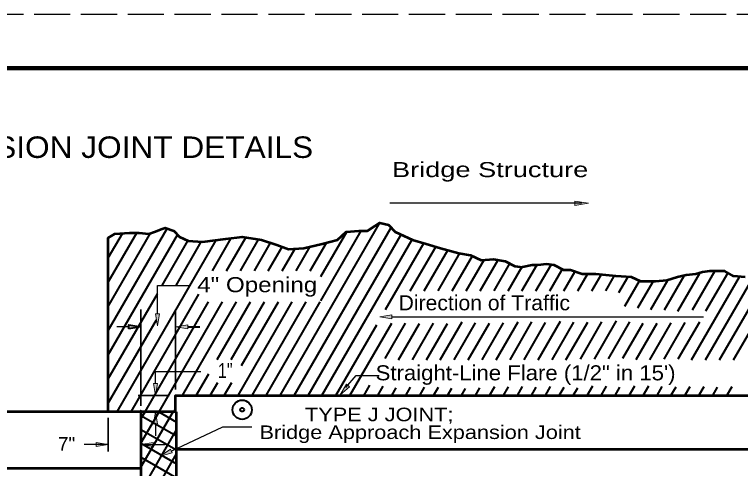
# Model space of a CAD drawing. Extents: x 14 to 49.3, y 28 to 50.
# Drawn here: x 36.45 to 43.21, y 45.82 to 50.04 of the extents above; entities that cross this region are included whole.
import ezdxf

# ---------------------------------------------------------------- set-up
doc = ezdxf.new("R2010")
doc.units = 0
doc.header["$LTSCALE"] = 0.056
doc.header["$PDMODE"] = 32
doc.header["$PDSIZE"] = 0.028
doc.linetypes.add('LONG_DASHED', pattern=[7.5, 6, -1.5])
for name, color, linetype, lineweight in [('1', 7, 'Continuous', 35), ('3', 7, 'Continuous', 13), ('6', 7, 'Continuous', 13)]:
    doc.layers.add(name, color=color, linetype=linetype, lineweight=lineweight)

msp = doc.modelspace()

# ---------------------------------------------------------------- hatches: boundary and pattern name
at = {"layer": '1'}
for points in [[(37.51475, 47.11892), (37.51475, 47.15642), (37.62725, 47.13758), (37.62725, 47.13758)], [(38.06233, 47.11892), (38.06233, 47.15642), (37.94983, 47.13758), (37.94983, 47.13758)], [(37.78058, 46.61067), (37.74308, 46.61067), (37.76183, 46.49817), (37.76183, 46.49817)], [(37.78058, 46.23517), (37.74308, 46.23517), (37.76183, 46.34767), (37.76183, 46.34767)], [(37.20992, 46.02475), (37.20992, 46.06225), (37.32242, 46.04342), (37.32242, 46.04342)], [(37.73975, 46.02475), (37.73975, 46.06225), (37.62725, 46.04342), (37.62725, 46.04342)]]:
    msp.add_hatch(color=256, dxfattribs=at).paths.add_polyline_path(points)
at = {"layer": '3'}
for points in [[(41.66558, 48.3085), (41.66558, 48.26683), (41.79058, 48.28767), (41.79058, 48.28767)], [(37.7985, 47.25958), (37.76092, 47.25958), (37.77975, 47.14708), (37.77975, 47.14708)], [(39.96283, 47.213), (39.96283, 47.2505), (39.85033, 47.23175), (39.85033, 47.23175)], [(39.56692, 46.5785), (39.5385, 46.603), (39.47925, 46.50558), (39.47925, 46.50558)], [(37.9165, 45.96458), (37.9005, 45.9985), (37.80658, 45.93392), (37.80658, 45.93392)]]:
    msp.add_hatch(color=256, dxfattribs=at).paths.add_polyline_path(points)

# ---------------------------------------------------------------- linework, layer by layer
at = {"layer": '1', "linetype": 'LONG_DASHED', "lineweight": 25}
msp.add_line((49.17658, 50.04392), (13.97658, 50.04392), dxfattribs=at)
at = {"layer": '1', "lineweight": 158}
msp.add_line((49.09325, 49.54392), (16.59325, 49.54392), dxfattribs=at)
at = {"layer": '1', "lineweight": 40}
for p, q in [((38.92158, 46.49817), (39.85, 48.10625)), ((37.3225, 47.1035), (37.8705, 48.05275)), ((39.0515, 46.49817), (39.95467, 48.06267)), ((39.301, 47.3805), (39.67675, 48.03117)), ((37.3225, 47.5535), (37.58742, 48.01233)), ((37.3225, 47.3285), (37.71508, 48.00858)), ((37.3225, 47.7785), (37.45483, 48.00783)), ((37.3225, 46.8785), (37.96692, 47.99467)), ((38.29233, 47.65825), (38.46783, 47.96233)), ((38.42225, 47.65825), (38.60183, 47.9695)), ((39.18133, 46.49817), (40.04675, 47.99708)), ((39.301, 47.6055), (39.54158, 48.02217)), ((37.40575, 46.34767), (38.32758, 47.94433)), ((37.82458, 47.52325), (38.06417, 47.93817)), ((37.95458, 47.52325), (38.1885, 47.92858)), ((38.55208, 47.65825), (38.72092, 47.95075)), ((38.682, 47.65825), (38.83242, 47.91875)), ((39.20158, 47.65825), (39.35233, 47.91942)), ((39.31125, 46.49817), (40.14908, 47.94933)), ((39.90358, 47.29925), (40.25933, 47.91533)), ((38.81192, 47.65825), (38.94108, 47.88208)), ((38.94183, 47.65825), (39.06175, 47.866)), ((39.07175, 47.65825), (39.20233, 47.88467)), ((40.13325, 47.472), (40.37092, 47.88367)), ((40.26317, 47.472), (40.48292, 47.8525)), ((40.39308, 47.472), (40.5955, 47.8225)), ((40.523, 47.472), (40.71058, 47.797)), ((40.65292, 47.472), (40.81958, 47.76075)), ((40.78283, 47.472), (40.94942, 47.76058)), ((40.91275, 47.472), (41.05933, 47.726)), ((41.04267, 47.472), (41.17042, 47.6935)), ((41.1725, 47.472), (41.31075, 47.7115)), ((41.30242, 47.472), (41.44292, 47.71533)), ((41.43233, 47.472), (41.54783, 47.67208)), ((41.56225, 47.472), (41.66525, 47.65042)), ((41.69217, 47.472), (41.7815, 47.62675)), ((42.62192, 47.2825), (42.827, 47.63775)), ((42.75958, 47.29592), (42.96692, 47.655)), ((42.88458, 47.28742), (43.08733, 47.63867)), ((41.822, 47.472), (41.9085, 47.62175)), ((41.95192, 47.472), (42.03125, 47.6095)), ((42.07267, 47.45608), (42.15617, 47.60075)), ((42.13042, 47.33117), (42.26625, 47.5665)), ((42.25042, 47.314), (42.393, 47.56092)), ((42.3725, 47.3005), (42.52967, 47.57275)), ((42.49983, 47.296), (42.683, 47.61325)), ((42.75083, 46.83067), (43.19675, 47.603)), ((42.88075, 46.83067), (43.31367, 47.5805)), ((43.01067, 46.83067), (43.42575, 47.54975)), ((37.3225, 46.6535), (37.77975, 47.4455)), ((37.53567, 46.34767), (38.167, 47.44133)), ((37.6655, 46.34767), (38.25592, 47.37025)), ((37.79542, 46.34767), (38.38583, 47.37025)), ((38.01217, 46.49817), (38.51575, 47.37025)), ((38.33508, 46.8325), (38.64567, 47.37025)), ((38.465, 46.8325), (38.7755, 47.37025)), ((38.53175, 46.49817), (39.03533, 47.37025)), ((38.56358, 46.77817), (38.90542, 47.37025)), ((38.66167, 46.49817), (39.16525, 47.37025)), ((38.79158, 46.49817), (39.29517, 47.37025)), ((43.1405, 46.83067), (43.45375, 47.37325)), ((37.3225, 46.4285), (37.77025, 47.20408)), ((39.44117, 46.49817), (39.82192, 47.15775)), ((39.57108, 46.49817), (39.96067, 47.17308)), ((39.90017, 46.843), (40.08983, 47.17175)), ((40.0235, 46.83183), (40.2185, 47.16958)), ((40.15275, 46.83067), (40.34983, 47.17208)), ((40.28267, 46.83067), (40.478, 47.16908)), ((40.41258, 46.83067), (40.6165, 47.184)), ((40.5425, 46.83067), (40.74133, 47.17525)), ((40.67233, 46.83067), (40.87, 47.173)), ((40.80225, 46.83067), (41.00108, 47.17508)), ((40.93217, 46.83067), (41.13575, 47.18333)), ((41.06208, 46.83067), (41.26542, 47.18283)), ((41.192, 46.83067), (41.39217, 47.17742)), ((41.32183, 46.83067), (41.52925, 47.18975)), ((41.45175, 46.83067), (41.65358, 47.18017)), ((41.58167, 46.83067), (41.78417, 47.18133)), ((41.71567, 46.83775), (41.9165, 47.18558)), ((41.84575, 46.83783), (42.05092, 47.19333)), ((41.97675, 46.84), (42.17592, 47.185)), ((42.10967, 46.84517), (42.29883, 47.17292)), ((42.23383, 46.83533), (42.42892, 47.17325)), ((42.36108, 46.83067), (42.56, 47.17525)), ((42.49483, 46.83733), (42.69158, 47.17817)), ((42.626, 46.83958), (42.82575, 47.1855)), ((38.06233, 47.13767), (38.17483, 47.13767)), ((38.14208, 46.49817), (38.2595, 46.70167)), ((38.272, 46.49817), (38.34283, 46.62092)), ((38.40192, 46.49817), (38.47275, 46.62092)), ((39.69933, 46.49517), (39.75683, 46.59483)), ((39.83083, 46.49817), (39.88217, 46.58708)), ((39.96075, 46.49817), (40.00258, 46.57067)), ((40.09067, 46.49817), (40.13625, 46.57708)), ((40.22058, 46.49817), (40.26508, 46.57525)), ((40.3505, 46.49817), (40.396, 46.57683)), ((40.48033, 46.49817), (40.51975, 46.56625)), ((40.61025, 46.49817), (40.64767, 46.563)), ((40.74017, 46.49817), (40.781, 46.56875)), ((40.87008, 46.49817), (40.9185, 46.582)), ((41, 46.49817), (41.04692, 46.57933)), ((41.12983, 46.49817), (41.17808, 46.58158)), ((41.25975, 46.49817), (41.30433, 46.57525)), ((41.38967, 46.49817), (41.43808, 46.58192)), ((41.51967, 46.49817), (41.565, 46.57675)), ((41.6495, 46.49817), (41.692, 46.57175)), ((41.77942, 46.49817), (41.83175, 46.58875)), ((41.90933, 46.49817), (41.96008, 46.58625)), ((42.03925, 46.49817), (42.08392, 46.57567)), ((42.16917, 46.49817), (42.22175, 46.58942)), ((42.299, 46.49817), (42.35158, 46.58942)), ((42.42892, 46.49817), (42.47783, 46.58292)), ((42.55883, 46.49817), (42.60558, 46.579)), ((42.68875, 46.49817), (42.73808, 46.5835)), ((42.81867, 46.49817), (42.86758, 46.58283)), ((42.9485, 46.49817), (42.99308, 46.57525)), ((43.07842, 46.49817), (43.127, 46.58208)), ((37.62725, 45.83133), (37.92533, 46.34767)), ((37.62725, 46.05633), (37.79542, 46.34767)), ((37.62725, 46.28133), (37.6655, 46.34767)), ((37.79375, 46.34767), (37.95883, 46.25233)), ((37.62725, 46.31392), (37.95883, 46.12242)), ((37.62725, 46.184), (37.95883, 45.9925)), ((37.62725, 45.60633), (37.95883, 46.18083)), ((37.62725, 46.05408), (37.95883, 45.86267)), ((37.62725, 45.38133), (37.95883, 45.95583)), ((37.62725, 45.92425), (37.95883, 45.73275))]:
    msp.add_line(p, q, dxfattribs=at)
at = {"layer": '1'}
for p, q in [((37.62725, 46.40383), (37.62725, 47.29967)), ((37.94983, 46.55433), (37.94983, 47.29967)), ((37.89358, 46.49817), (37.59983, 46.49817)), ((37.32242, 46.29133), (37.32242, 45.97842))]:
    msp.add_line(p, q, dxfattribs=at)
at = {"layer": '1', "lineweight": 25}
for p, q in [((37.51475, 47.13767), (37.40225, 47.13767)), ((37.76183, 46.61067), (37.76183, 46.72317)), ((37.76183, 46.72317), (38.18467, 46.72317)), ((37.76183, 46.23517), (37.76183, 46.12267)), ((37.32242, 46.04342), (37.09742, 46.04342)), ((37.62725, 46.04342), (37.85217, 46.04342))]:
    msp.add_line(p, q, dxfattribs=at)
at = {"layer": '1', "lineweight": 13}
for p, q in [((41.12983, 46.49817), (41.15558, 46.54267)), ((39.701, 46.49817), (39.712, 46.51733)), ((37.89358, 46.34767), (37.59983, 46.34767)), ((37.92533, 46.34767), (37.94983, 46.39025)), ((37.62717, 46.18625), (37.62717, 46.30242))]:
    msp.add_line(p, q, dxfattribs=at)
at = {"layer": '1', "lineweight": 53}
for p, q in [((37.3225, 46.34767), (32.61783, 46.34767)), ((37.94983, 46.34767), (37.3225, 46.34767)), ((37.62725, 46.34767), (37.62725, 44.664)), ((37.95883, 44.664), (37.95883, 46.34767)), ((37.95883, 45.99975), (43.39992, 45.99975)), ((37.62725, 45.821), (32.61783, 45.821))]:
    msp.add_line(p, q, dxfattribs=at)
for points in [[(37.3225, 46.34767), (37.3225, 47.96533), (37.38517, 48.003), (37.51967, 48.01233), (37.60925, 48.01233), (37.69892, 48.003), (37.75267, 48.02183), (37.8245, 48.05), (37.85133, 48.05942), (37.932, 48.03117), (37.98575, 47.97475), (38.0665, 47.93717), (38.20092, 47.92775), (38.41608, 47.956), (38.56842, 47.97475), (38.74775, 47.94658), (38.89108, 47.89958), (38.99867, 47.86192), (39.14217, 47.87125), (39.31242, 47.90892), (39.45583, 47.94658), (39.5365, 48.02183), (39.653, 48.03117), (39.73375, 48.03117), (39.80542, 48.07825), (39.85025, 48.10642), (39.93092, 48.08767), (39.99367, 48.02183), (40.155, 47.94658), (40.2805, 47.90892), (40.415, 47.87125), (40.58525, 47.82425), (40.69283, 47.8055), (40.7915, 47.7585), (40.90792, 47.76783), (41.01558, 47.749), (41.10517, 47.702), (41.17692, 47.69267)], [(43.24767, 47.59858), (43.14, 47.608), (43.05942, 47.655), (42.97867, 47.655), (42.91592, 47.655), (42.85325, 47.64558), (42.79042, 47.62675), (42.70083, 47.61742), (42.62008, 47.59858), (42.52158, 47.57042), (42.41392, 47.56092), (42.35125, 47.56092), (42.2795, 47.56092), (42.18992, 47.59858), (42.04642, 47.608), (41.85817, 47.62675), (41.73275, 47.62675), (41.62517, 47.66442), (41.56242, 47.66442), (41.47275, 47.7115), (41.40108, 47.72083), (41.32033, 47.7115), (41.26658, 47.7115), (41.17692, 47.69267)], [(37.94983, 46.34767), (37.94983, 46.49817), (43.45375, 46.49817), (43.45375, 47.54208)]]:
    msp.add_lwpolyline(points, dxfattribs=at)
at = {"layer": '1', "lineweight": 40}
msp.add_lwpolyline([(37.51475, 47.11892), (37.51475, 47.15642), (37.62725, 47.13758), (37.62725, 47.13758)], close=True, dxfattribs=at)
at = {"layer": '1', "lineweight": 13}
for points in [[(38.06233, 47.11892), (38.06233, 47.15642), (37.94983, 47.13758), (37.94983, 47.13758)], [(37.78058, 46.61067), (37.74308, 46.61067), (37.76183, 46.49817), (37.76183, 46.49817)], [(37.78058, 46.23517), (37.74308, 46.23517), (37.76183, 46.34767), (37.76183, 46.34767)], [(37.20992, 46.02475), (37.20992, 46.06225), (37.32242, 46.04342), (37.32242, 46.04342)], [(37.73975, 46.02475), (37.73975, 46.06225), (37.62725, 46.04342), (37.62725, 46.04342)]]:
    msp.add_lwpolyline(points, close=True, dxfattribs=at)
at = {"layer": '3', "lineweight": 25}
for p, q in [((41.72975, 48.28767), (39.9425, 48.28767)), ((39.96283, 47.23175), (42.86217, 47.23175))]:
    msp.add_line(p, q, dxfattribs=at)
at = {"layer": '3'}
for points in [[(41.66558, 48.3085), (41.66558, 48.26683), (41.79058, 48.28767), (41.79058, 48.28767)], [(37.7985, 47.25958), (37.76092, 47.25958), (37.77975, 47.14708), (37.77975, 47.14708)], [(39.96283, 47.213), (39.96283, 47.2505), (39.85033, 47.23175), (39.85033, 47.23175)], [(39.56692, 46.5785), (39.5385, 46.603), (39.47925, 46.50558), (39.47925, 46.50558)], [(37.9165, 45.96458), (37.9005, 45.9985), (37.80658, 45.93392), (37.80658, 45.93392)]]:
    msp.add_lwpolyline(points, close=True, dxfattribs=at)
at = {"layer": '3', "lineweight": 25}
for points in [[(37.77975, 47.25958), (37.77975, 47.52325), (38.0845, 47.52325)], [(39.533, 46.5735), (39.62975, 46.68575), (39.845, 46.68575)], [(37.9085, 45.98158), (38.38925, 46.20658), (38.65825, 46.20658)]]:
    msp.add_lwpolyline(points, dxfattribs=at)
at = {"layer": '3', "lineweight": 40}
for radius in [0.08964, 0.01793]:
    msp.add_circle((38.56861, 46.36648), radius, dxfattribs=at)
at = {"layer": '6'}
for p, q in [((37.94983, 47.13767), (37.94992, 47.13767)), ((37.76183, 46.49817), (37.76192, 46.49817)), ((37.94983, 46.49817), (37.94992, 46.49817)), ((37.94983, 46.49808), (37.94992, 46.49808)), ((37.32242, 46.34758), (37.3225, 46.34758)), ((37.94983, 46.34767), (37.94992, 46.34767)), ((37.32242, 46.14042), (37.3225, 46.14042)), ((37.62717, 46.13), (37.62725, 46.13))]:
    msp.add_line(p, q, dxfattribs=at)
msp.add_point((37.62725, 46.34758), dxfattribs=at)

# ---------------------------------------------------------------- texts
at = {"layer": '1'}
for s, height, width, p in [('1"', 0.14, 0.8, (38.34325, 46.66058)), ('7"', 0.126, 1.05, (36.854, 45.98608))]:
    msp.add_text(s, height=height, dxfattribs=dict(at, width=width)).set_placement(p)
at = {"layer": '3'}
for s, height, width, p in [('MEDIAN BARRIER EXPANSION JOINT DETAILS', 0.2, 1.1, (32.65758, 48.7095)), ('Bridge Structure', 0.14, 1.35, (39.963, 48.53092)), ('4" Opening', 0.14, 1.2, (38.15075, 47.46033)), ('Direction of Traffic', 0.14, 1.05, (40.02433, 47.29158)), ('Straight-Line Flare (1/2" in 15\')', 0.14, 1.1, (39.8105, 46.64)), ('TYPE J JOINT;', 0.126, 1.2, (39.15333, 46.25967)), ('Bridge Approach Expansion Joint', 0.126, 1.2, (38.72992, 46.09417))]:
    msp.add_text(s, height=height, dxfattribs=dict(at, width=width)).set_placement(p)

doc.saveas('drawing.dxf')
